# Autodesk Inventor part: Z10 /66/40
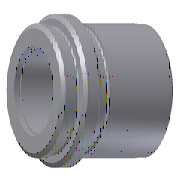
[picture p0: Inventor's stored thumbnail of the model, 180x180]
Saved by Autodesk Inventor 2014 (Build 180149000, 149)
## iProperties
IsCustomPart: 0
Created: 2009-11
Part Number: Z10 /66/40
Material: DIN 1.7131
Description: guide bush
Document SubType Name: Modeling
Designer: gaom
Standard Revision: 1
Manufacturer: HASCO
Language: en-US
Size Designation: 66/40
Categories: <MemberInstance><Categories><Category DisplayName="Mold" InternalName="349578f2-f4d4-4954-8c09-8e99297a61c0" Mnemonic="MOLD"><Category DisplayName="Guide Compon
Density: 7.85 g/cm^3
Appearance: Default
Author: gaom
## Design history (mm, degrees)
sketch "Sketch1"
  geometry: L1 (0, -16.8)-(0, 9.8) reference; L2 (0, 22)-(27, 22); L3 (27, 22)-(27, 11); L4 (27, 11)-(26.5, 11); L5 (26.5, 11)-(26.5, 10); L6 (26.5, 10)-(30, 10); L7 (30, 10)-(30, 0); L8 (30, 0)-(26.5, 0); L9 (26.5, 0)-(26.5, -1); L10 (26.5, -1)-(27, -1); L11 (27, -1)-(27, -55); L12 (27, -55)-(26.95, -55); L13 (26.95, -55)-(26.95, -56); L14 (26.95, -56)-(0, -56); L15 (0, 22)-(0, -56); 1 further point
  constraints: 28 end point, 7 parallel, 5 perpendicular, 2 collinear, 2 equal length, 2 point on line, 1 horizontal alignment
  dimensions: "d0" = 54 diameter of L11 L1 (= D); "d2" = 1 distance between parallel lines of L14 L12; "d27" = 53.9 diameter of L13 L1 (= D_Guide); "d4" = 60 diameter of L7 L1 (= D2); "d5" = 54 diameter of L3 L1 (= D1); "d6" = 10 distance between parallel lines of L8 L6 (= H_); "d7" = 66 distance between parallel lines of L14 L6 (= L); "d8" = 12 distance between parallel lines of L6 L2 (= L1); "d9" = 1 distance between parallel lines of L10 L8; "d10" = 0.5 distance between parallel lines of L11 L9
revolve "Revolution1" sketch "Sketch1" stored, may be unused: angle "d11" = 90 deg
sketch "Sketch2"
  geometry: L1 (-26.95, -56)-(26.95, -56) reference; L2 (20, -56)-(20, 22); L3 (20, 22)-(20, 22); L4 (20, 22)-(20, 100); L5 (0, -56)-(0, 100); L6 (0, 100)-(20, 100); L7 (20, -56)-(0, -56)
  constraints: 12 end point, 3 perpendicular, 2 collinear, 1 midpoint, 1 parallel, 1 point on line
  dimensions: "d12" = 40 diameter of L2 L5 (= d_); "d13" = 78 distance of L2.start L2.end (= l_); "d14" = 78 distance of L3.end L4.end (= L + L1); "d15" = 40 diameter of L4 L5 (= d3)
revolve "Revolution2" sketch "Sketch2" stored, may be unused: angle "d16" = 90 deg
chamfer "Chamfer1" distance "d17" = 0.5; stored, may be unused: second distance "d18" = 2, angle "d19" = 45 deg
fillet "Fillet1" dims "d20" = 0.3
fillet "Fillet2" dims "d21" = 0.8
body "Solid1"
other parameters: "d_" = 40 [user parameter; used in 1 equation term], "L" = 66 [user parameter; used in 2 equation terms], "D" = 54 [user parameter; used in 1 equation term], "D1" = 54 [user parameter; used in 1 equation term], "D2" = 60 [user parameter; used in 1 equation term], "H_" = 10 [user parameter; used in 1 equation term], "L1" = 12 [user parameter; used in 2 equation terms], "l_" = 78 [user parameter; used in 1 equation term], "d3" = 40 [user parameter; used in 1 equation term], "D_Guide" = 53.9 [user parameter; used in 1 equation term], "d22" = 0, "d23" = 0, "d24" = 0, "d25" = 0, "d26" = 0
